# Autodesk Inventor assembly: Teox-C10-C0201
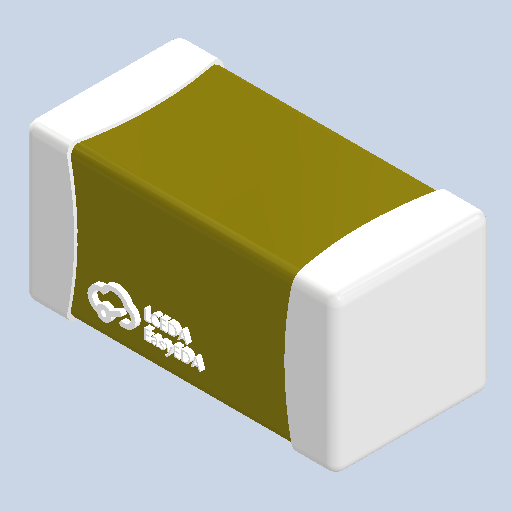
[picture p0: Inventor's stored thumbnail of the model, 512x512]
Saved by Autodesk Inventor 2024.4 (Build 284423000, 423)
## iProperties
Created: 2025-05
Part Number: Teox-C10-C0201
Document SubType Name: Assembly
Designer: AdminForWorker
Title: Teox-C10-C0201
Author: AdminForWorker
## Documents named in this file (2)
- c:\worker\convert-fusion-r02-cosv3\tmp\job-1\2\temp\files\be827049-a7f2-47ea-a815-8d9efd6bfce9\Teox-C10-C0201.iam
- c:\worker\convert-fusion-r02-cosv3\tmp\job-1\2\temp\files\be827049-a7f2-47ea-a815-8d9efd6bfce9\COMPOUND (3).ipt
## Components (1 placed, 1 different names)
1. COMPOUND (3):3
